Omron CX-Programmer project NewProject (CX-Programmer 7.20)

# PLC NewPLC1: CP1H Y
I/O table (CPU CJ1M-CPU21): rack 0 slot 0 CJ1W-DRM21; rack 0 slot 1 CJ1W-MAD42

## Global symbols (name address type ; comment)
W1.00 BOOL  ; W1.01
CCW_Limit_Flag A540.09 BOOL
CW_Limit_Flag A540.08 BOOL

## Program NewProgram1 (cyclic task 0)
Local symbols
CCW_INPUT 0.01 BOOL
CW_INPUT 0.04 BOOL  ; SMART STEP CW INPUT
ESTOP_PB 1.04 BOOL  ; E-STOP PB
ESTOP_hmi 50.03 BOOL
IN_PSN A280.03 BOOL  ; IN POSITION BIT
JOG_CCW 0.00 BOOL  ; JOG COUNTER CLOCK WISE
JOG_CW 0.10 BOOL  ; JOG CLOCK WISE
JOG_SPD_LWRWRD D0 CHANNEL  ; JOG SPEED LOWER WORD
JOG_SPD_UPRWRD D1 CHANNEL  ; JOG SPEED UPPER WORD
MOVE1_ACCRATE D100 CHANNEL  ; MOVE #1 ACCELERATION RATE
MOVE1_CM W100.05 BOOL  ; MOVE #1 COMPLETE BIT
MOVE1_CM_DELAY W100.06 BOOL  ; MOVE #1 COMPLETE DELAY BIT
MOVE1_CM_DTIM_DN T0000 BOOL  ; MOVE #1 COMPLETE DELAY TIMER DONE BIT
MOVE1_DECELRATE D101 CHANNEL  ; MOVE #1 DECELERATION RATE
MOVE1_FSPD_LWRWRD D102 CHANNEL  ; MOVE #1 FINAL SPEED LOWER WORD
MOVE1_FSPD_UPRWRD D103 CHANNEL  ; MOVE #1 FINAL SPEED UPPER WORD
MOVE1_PSN_LWRWRD D104 CHANNEL  ; MOVE #1 POSITION LOWER WORD
MOVE1_PSN_UPRWRD D105 CHANNEL  ; MOVE #1 POSTION UPPER WORD
MOVE1_ST W100.04 BOOL  ; MOVE #1 START BIT
MOVE1_STSPD_LWRWRD D110 CHANNEL  ; MOVE #1 STARTING SPEED LOWER WORD
MOVE1_STSPD_UPRWRD D111 CHANNEL  ; MOVE # 1 STARTING SPEED UPPER WORD
MOVE2_ACCELRATE D200 CHANNEL  ; MOVE #2 ACCELERATION RATE
MOVE2_CM W100.08 BOOL  ; MOVE #2 COMPLETE BIT
MOVE2_CM_DELAY W100.09 BOOL  ; MOVE #2 COMPLETE DELAY BIT
MOVE2_CM_DTIM_DN T0001 BOOL  ; MOVE #2 COMPLETE DELAY TIMER DONE BIT
MOVE2_DECELRATE D201 CHANNEL  ; MOVE #2 DECELERATION RATE
MOVE2_FSPD_LWRWRD D202 CHANNEL  ; MOVE #2 FINAL SPEED LOWER WORD
MOVE2_FSPD_UPRWRD D203 CHANNEL  ; MOVE #2 FINAL SPEED UPPER WORD
MOVE2_PSN_LWRWRD D204 CHANNEL  ; MOVE #2 POSITION LOWER WORD
MOVE2_PSN_UPRWRD D205 CHANNEL  ; MOVE #2 POSITION UPPER WORD
MOVE2_ST W100.07 BOOL  ; MOVE #2 START BIT
MOVE2_STSPD_LWRWRD D210 CHANNEL  ; MOVE #2 START SPEED LOWER WORD
MOVE2_STSPD_UPRWRD D211 CHANNEL  ; MOVE #2 START SPEED UPPER WORD
MOVE3_ACCELRATE D300 CHANNEL  ; MOVE #3 ACCELERATION RATE
MOVE3_CM W100.11 BOOL  ; MOVE #3 COMPLETE BIT
MOVE3_CM_DELAY W100.12 BOOL  ; MOVE #3 COMPLETE DELAY BIT
MOVE3_CM_DTIM_DN T0002 BOOL  ; MOVE #3 COMPLETE DELAY TIMER  DONE BIT
MOVE3_DECELRATE D301 CHANNEL  ; MOVE #3 DECELERATION RATE
MOVE3_FSPD_LWRWRD D302 CHANNEL  ; MOVE #3 FINAL SPEED LOWER WORD
MOVE3_FSPD_UPRWRD D303 CHANNEL  ; MOVE #3 FINAL SPEED UPPER WORD
MOVE3_PSN_LWRWRD D304 CHANNEL  ; MOVE #3 POSITION LOWER WORD
MOVE3_PSN_UPRWRD D305 CHANNEL  ; MOVE #3 POSITION UPPER WORD
MOVE3_ST W100.10 BOOL  ; MOVE #3 START BIT
MOVE3_STSPD_LWRWRD D310 CHANNEL  ; MOVE #3 START SPEED LOWER WORD
MOVE3_STSPD_UPRWRD D311 CHANNEL  ; MOVE #3 START SPEED UPPER WORD
MOVE4_ACCELRATE D400 CHANNEL  ; MOVE #4 ACCELERATION RATE
MOVE4_CM W100.14 BOOL  ; MOVE #4 COMPLETE BIT
MOVE4_DECELRATE D401 CHANNEL  ; MOVE #4 DECELERATION RATE
MOVE4_FSPD_LWRWRD D402 CHANNEL  ; MOVE #4 FINAL SPEED LOWER WORD
MOVE4_FSPD_UPRWRD D403 CHANNEL  ; MOVE #4 FINAL SPEED UPPER WORD
MOVE4_PSN_LWRWRD D404 CHANNEL  ; MOVE #4 POSITION LOWER WORD
MOVE4_PSN_UPRWRD D405 CHANNEL  ; MOVE #4 POSITION UPPER WORD
MOVE4_ST W100.13 BOOL  ; MOVE #4 START BIT
MOVE4_STSPD_LWRWRD D410 CHANNEL  ; MOVE #4 START SPEED LOWER WORD
MOVE4_STSPD_UPRWRD D411 CHANNEL  ; MOVE #4 START SPEED UPPER WORD
MOVES_RESET W100.15 BOOL  ; MOVES RESET BIT
MOVE_CM A280.03 BOOL  ; MOVE COMPLETE BIT
ORGEN_TS 0.11 BOOL  ; ORIGIN ENABLE TOUCH SWITCH
ORG_EST A280.05 BOOL  ; ORIGIN ESTABLISHED
ORG_SRCHCM W100.01 BOOL  ; ORIGIN SEARCH COMPLETE
ORG_SRCHEN W100.00 BOOL  ; ORIGIN SEARCH ENABLE BIT
PV_LWRWRD A276 CHANNEL  ; PV LOWER WORD
PV_UPRWRD A277 CHANNEL  ; PV UPPER WORD
SSTEP_CCW A540.08 BOOL  ; SMART STEP CCW OVER TRAVEL
SSTEP_CCWEN_OUT 100.00 BOOL  ; SMART STEP CCW ENABLE OUTPUT
SSTEP_CW A540.09 BOOL  ; SMART STEP CW OVER TRAVEL
SSTEP_CWEN_OUT 100.01 BOOL  ; SMART STEP CW ENABLE OUTPUT
SSTEP_HOME W100.02 BOOL  ; SMART STEP HOME
SSTEP_JOGEN W100.03 BOOL  ; SMART STEP JOGGING ENABLE BIT
SSTEP_MOV1EN_TS 0.05 BOOL  ; SMART STEP MOVE #1 ENABLE TOUCH SWITCH
SSTEP_ORGPRX_OUT 100.02 BOOL  ; SMART STEP ORIGIN PROXIMITY OUTPUT
SSTEP_RUNEN_OUT 100.03 BOOL  ; SMART STEP RUN ENABLE OUTPUT
STOP_SPD_LWRWRD D2 CHANNEL  ; STOP SPEED LOWER WORD
STOP_SPD_UPPWRD D3 CHANNEL  ; STOP SPEED UPPER WORD
STPD_ORG A280.06 BOOL  ; STOPPED AT ORIGIN
control_on 75.00 BOOL
convert_pulses D80 DINT
estop_work 60.00 BOOL
go 50.02 BOOL
jog_ccw 50.04 BOOL
jog_cw 50.01 BOOL
jogging_work 60.01 BOOL
latch_rev1 70.00 BOOL
latch_rev2 70.01 BOOL
latch_rev3 70.02 BOOL
latch_rev4 70.03 BOOL
mov1_hmi D250 CHANNEL  ; move 1 position converted for hmi
mov2_hmi D260 CHANNEL  ; move 2 position converted for hmi
mov3_hmi D270 CHANNEL  ; move 3 position converted for hmi
mov4_hmi D280 CHANNEL  ; move 4 position converted for hmi
origin_serach 50.00 BOOL
pulses_good 75.01 BOOL  ; Pulses are over #13CC for /
recipe_controlword D50 CHANNEL  ; gp pro ex recipe control word
rev1_go 60.05 BOOL
rev2_go 60.06 BOOL
rev3_go 60.07 BOOL
rev4_go 60.08 BOOL
revolutions D78 CHANNEL  ; number of revolutions the motor made
smartstep_ccw_jog 50.05 BOOL
temp_off 70.04 BOOL
timer10_done T0010 BOOL
timer11_done T0011 BOOL
timer12_done T0012 BOOL
timer13_done T0013 BOOL

### Section Moves

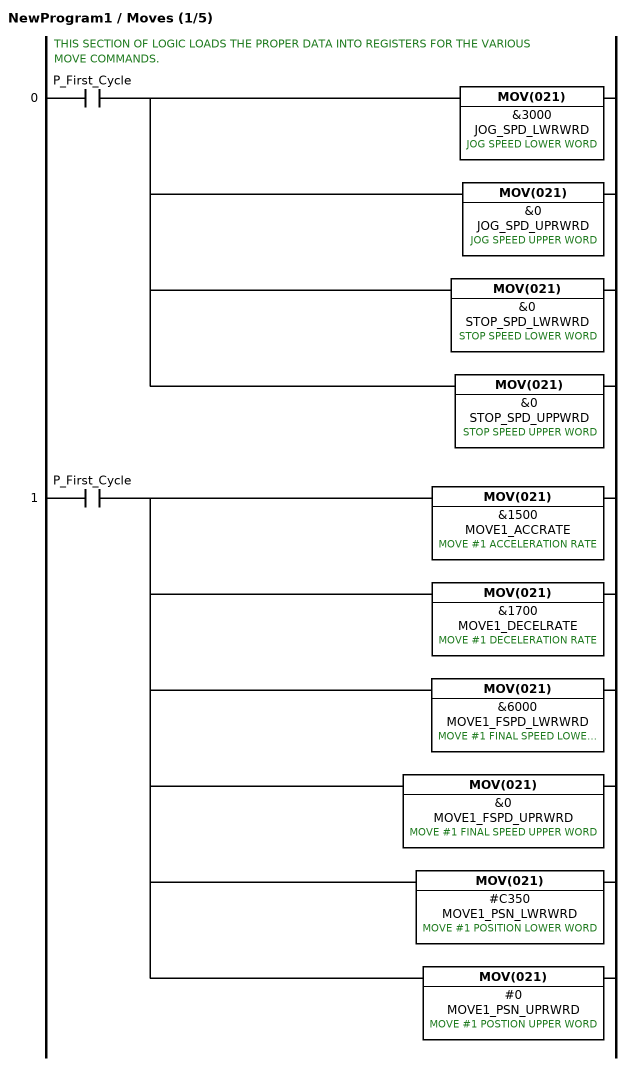
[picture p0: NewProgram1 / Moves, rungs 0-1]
; rung 0: THIS SECTION OF LOGIC LOADS THE PROPER DATA INTO REGISTERS FOR THE VARIOUS MOVE COMMANDS.
LD P_First_Cycle
MOV(021) &3000 JOG_SPD_LWRWRD  ; JOG SPEED LOWER WORD
MOV(021) &0 JOG_SPD_UPRWRD  ; JOG SPEED UPPER WORD
MOV(021) &0 STOP_SPD_LWRWRD  ; STOP SPEED LOWER WORD
MOV(021) &0 STOP_SPD_UPPWRD  ; STOP SPEED UPPER WORD
; rung 1
LD P_First_Cycle
MOV(021) &1500 MOVE1_ACCRATE  ; MOVE #1 ACCELERATION RATE
MOV(021) &1700 MOVE1_DECELRATE  ; MOVE #1 DECELERATION RATE
MOV(021) &6000 MOVE1_FSPD_LWRWRD  ; MOVE #1 FINAL SPEED LOWER WORD
MOV(021) &0 MOVE1_FSPD_UPRWRD  ; MOVE #1 FINAL SPEED UPPER WORD
MOV(021) #C350 MOVE1_PSN_LWRWRD  ; MOVE #1 POSITION LOWER WORD
MOV(021) #0 MOVE1_PSN_UPRWRD  ; MOVE #1 POSTION UPPER WORD

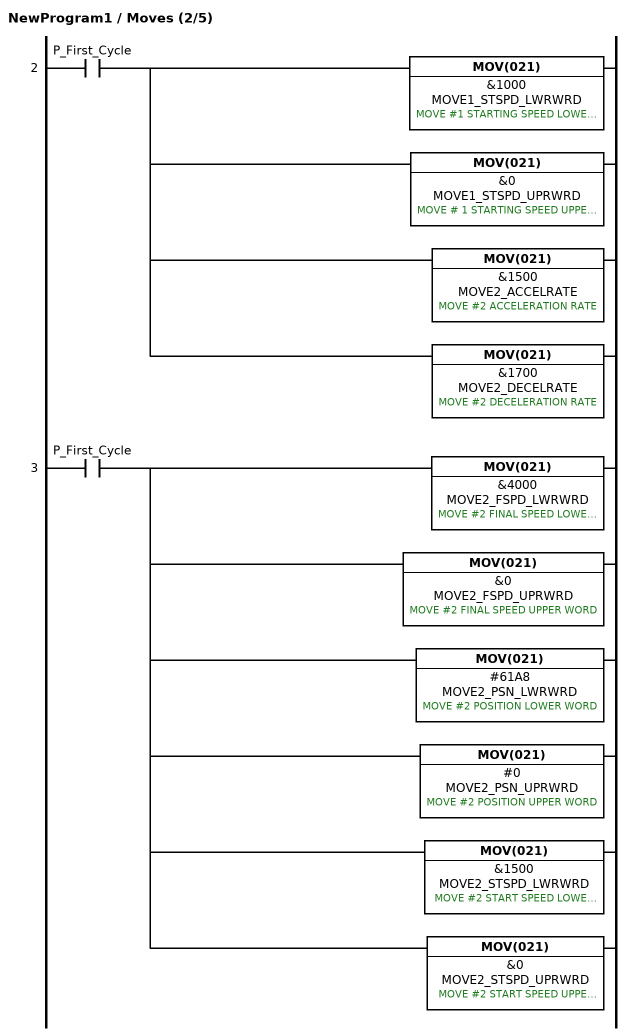
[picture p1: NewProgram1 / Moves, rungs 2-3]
; rung 2
LD P_First_Cycle
MOV(021) &1000 MOVE1_STSPD_LWRWRD  ; MOVE #1 STARTING SPEED LOWER WORD
MOV(021) &0 MOVE1_STSPD_UPRWRD  ; MOVE # 1 STARTING SPEED UPPER WORD
MOV(021) &1500 MOVE2_ACCELRATE  ; MOVE #2 ACCELERATION RATE
MOV(021) &1700 MOVE2_DECELRATE  ; MOVE #2 DECELERATION RATE
; rung 3
LD P_First_Cycle
MOV(021) &4000 MOVE2_FSPD_LWRWRD  ; MOVE #2 FINAL SPEED LOWER WORD
MOV(021) &0 MOVE2_FSPD_UPRWRD  ; MOVE #2 FINAL SPEED UPPER WORD
MOV(021) #61A8 MOVE2_PSN_LWRWRD  ; MOVE #2 POSITION LOWER WORD
MOV(021) #0 MOVE2_PSN_UPRWRD  ; MOVE #2 POSITION UPPER WORD
MOV(021) &1500 MOVE2_STSPD_LWRWRD  ; MOVE #2 START SPEED LOWER WORD
MOV(021) &0 MOVE2_STSPD_UPRWRD  ; MOVE #2 START SPEED UPPER WORD

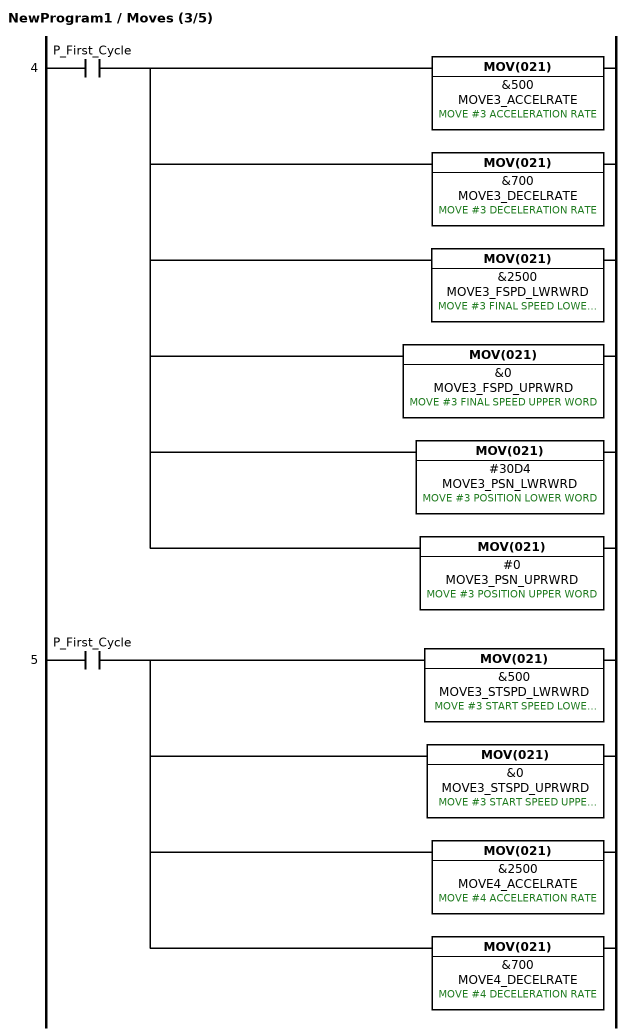
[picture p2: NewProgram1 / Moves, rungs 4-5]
; rung 4
LD P_First_Cycle
MOV(021) &500 MOVE3_ACCELRATE  ; MOVE #3 ACCELERATION RATE
MOV(021) &700 MOVE3_DECELRATE  ; MOVE #3 DECELERATION RATE
MOV(021) &2500 MOVE3_FSPD_LWRWRD  ; MOVE #3 FINAL SPEED LOWER WORD
MOV(021) &0 MOVE3_FSPD_UPRWRD  ; MOVE #3 FINAL SPEED UPPER WORD
MOV(021) #30D4 MOVE3_PSN_LWRWRD  ; MOVE #3 POSITION LOWER WORD
MOV(021) #0 MOVE3_PSN_UPRWRD  ; MOVE #3 POSITION UPPER WORD
; rung 5
LD P_First_Cycle
MOV(021) &500 MOVE3_STSPD_LWRWRD  ; MOVE #3 START SPEED LOWER WORD
MOV(021) &0 MOVE3_STSPD_UPRWRD  ; MOVE #3 START SPEED UPPER WORD
MOV(021) &2500 MOVE4_ACCELRATE  ; MOVE #4 ACCELERATION RATE
MOV(021) &700 MOVE4_DECELRATE  ; MOVE #4 DECELERATION RATE

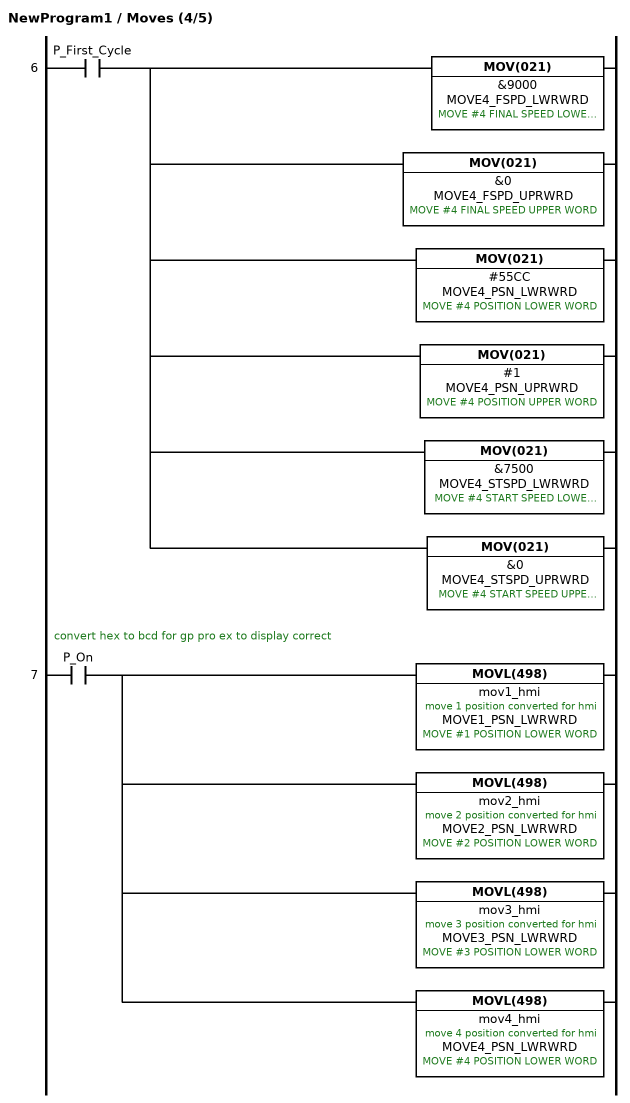
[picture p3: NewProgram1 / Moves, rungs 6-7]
; rung 6
LD P_First_Cycle
MOV(021) &9000 MOVE4_FSPD_LWRWRD  ; MOVE #4 FINAL SPEED LOWER WORD
MOV(021) &0 MOVE4_FSPD_UPRWRD  ; MOVE #4 FINAL SPEED UPPER WORD
MOV(021) #55CC MOVE4_PSN_LWRWRD  ; MOVE #4 POSITION LOWER WORD
MOV(021) #1 MOVE4_PSN_UPRWRD  ; MOVE #4 POSITION UPPER WORD
MOV(021) &7500 MOVE4_STSPD_LWRWRD  ; MOVE #4 START SPEED LOWER WORD
MOV(021) &0 MOVE4_STSPD_UPRWRD  ; MOVE #4 START SPEED UPPER WORD
; rung 7: convert hex to bcd for gp pro ex to display correct
LD P_On
MOVL(498) mov1_hmi MOVE1_PSN_LWRWRD  ; move 1 position converted for hmi, MOVE #1 POSITION LOWER WORD
MOVL(498) mov2_hmi MOVE2_PSN_LWRWRD  ; move 2 position converted for hmi, MOVE #2 POSITION LOWER WORD
MOVL(498) mov3_hmi MOVE3_PSN_LWRWRD  ; move 3 position converted for hmi, MOVE #3 POSITION LOWER WORD
MOVL(498) mov4_hmi MOVE4_PSN_LWRWRD  ; move 4 position converted for hmi, MOVE #4 POSITION LOWER WORD

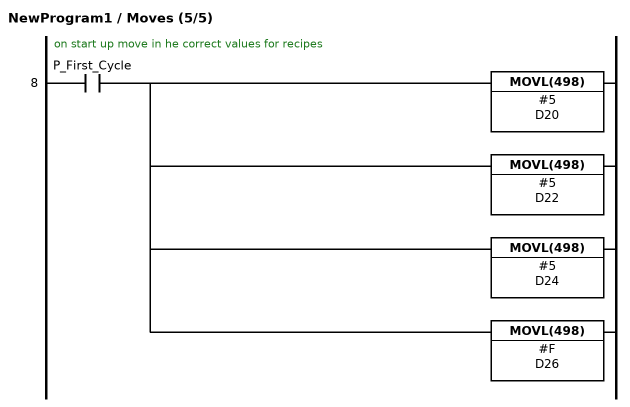
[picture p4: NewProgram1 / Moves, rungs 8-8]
; rung 8: on start up move in he correct values for recipes
LD P_First_Cycle
MOVL(498) #5 D20
MOVL(498) #5 D22
MOVL(498) #5 D24
MOVL(498) #F D26

### Section Main

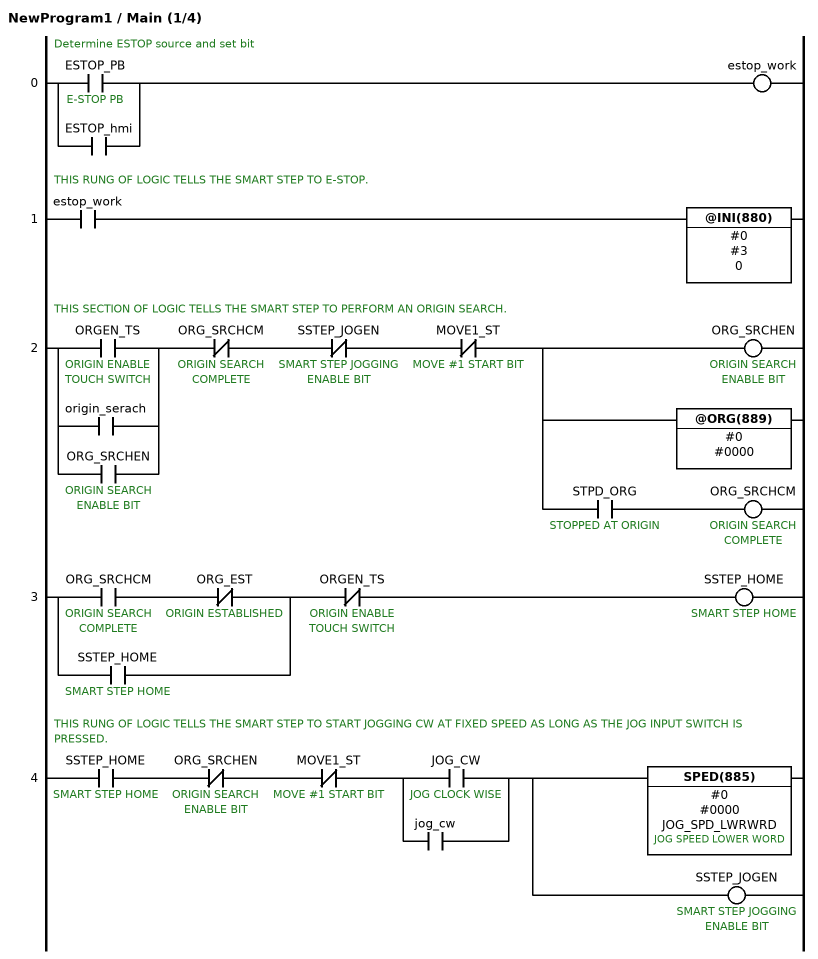
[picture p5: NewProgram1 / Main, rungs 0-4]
; rung 0: Determine ESTOP source and set bit
LD ESTOP_PB  ; E-STOP PB
OR ESTOP_hmi
OUT estop_work
; rung 1: THIS RUNG OF LOGIC TELLS THE SMART STEP TO E-STOP.
LD estop_work
@INI(880) #0 #3 0
; rung 2: THIS SECTION OF LOGIC TELLS THE SMART STEP TO PERFORM AN ORIGIN SEARCH.
LD ORGEN_TS  ; ORIGIN ENABLE TOUCH SWITCH
OR origin_serach
OR ORG_SRCHEN  ; ORIGIN SEARCH ENABLE BIT
ANDNOT ORG_SRCHCM  ; ORIGIN SEARCH COMPLETE
ANDNOT SSTEP_JOGEN  ; SMART STEP JOGGING ENABLE BIT
ANDNOT MOVE1_ST  ; MOVE #1 START BIT
OUT ORG_SRCHEN  ; ORIGIN SEARCH ENABLE BIT
@ORG(889) #0 #0000
AND STPD_ORG  ; STOPPED AT ORIGIN
OUT ORG_SRCHCM  ; ORIGIN SEARCH COMPLETE
; rung 3
LD ORG_SRCHCM  ; ORIGIN SEARCH COMPLETE
ANDNOT ORG_EST  ; ORIGIN ESTABLISHED
OR SSTEP_HOME  ; SMART STEP HOME
ANDNOT ORGEN_TS  ; ORIGIN ENABLE TOUCH SWITCH
OUT SSTEP_HOME  ; SMART STEP HOME
; rung 4: THIS RUNG OF LOGIC TELLS THE SMART STEP TO START JOGGING CW AT FIXED SPEED AS LONG AS THE JOG INPUT SWITCH IS PRESSED.
LD SSTEP_HOME  ; SMART STEP HOME
ANDNOT ORG_SRCHEN  ; ORIGIN SEARCH ENABLE BIT
ANDNOT MOVE1_ST  ; MOVE #1 START BIT
LD JOG_CW  ; JOG CLOCK WISE
OR jog_cw
ANDLD
SPED(885) #0 #0000 JOG_SPD_LWRWRD  ; JOG SPEED LOWER WORD
OUT SSTEP_JOGEN  ; SMART STEP JOGGING ENABLE BIT

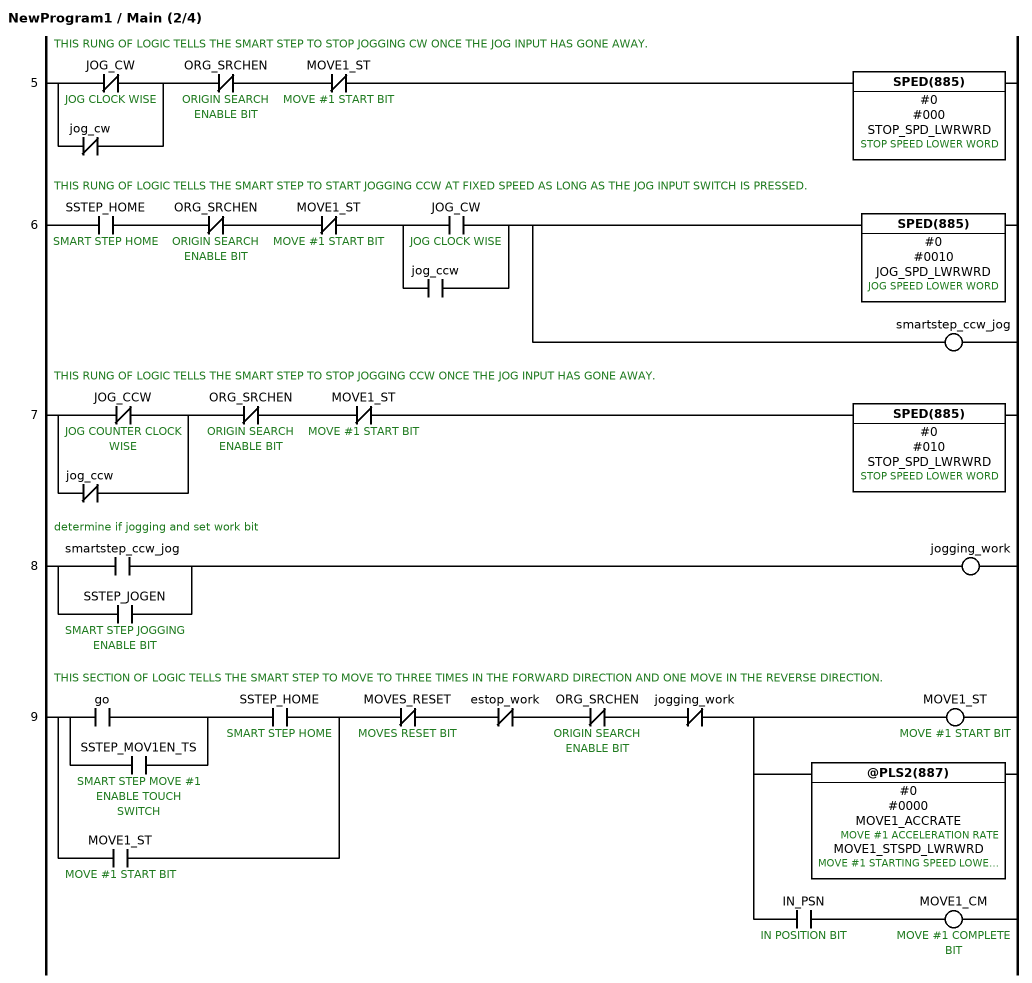
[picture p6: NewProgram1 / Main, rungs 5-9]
; rung 5: THIS RUNG OF LOGIC TELLS THE SMART STEP TO STOP JOGGING CW ONCE THE JOG INPUT HAS GONE AWAY.
LDNOT JOG_CW  ; JOG CLOCK WISE
ORNOT jog_cw
ANDNOT ORG_SRCHEN  ; ORIGIN SEARCH ENABLE BIT
ANDNOT MOVE1_ST  ; MOVE #1 START BIT
SPED(885) #0 #000 STOP_SPD_LWRWRD  ; STOP SPEED LOWER WORD
; rung 6: THIS RUNG OF LOGIC TELLS THE SMART STEP TO START JOGGING CCW AT FIXED SPEED AS LONG AS THE JOG INPUT SWITCH IS PRESSED.
LD SSTEP_HOME  ; SMART STEP HOME
ANDNOT ORG_SRCHEN  ; ORIGIN SEARCH ENABLE BIT
ANDNOT MOVE1_ST  ; MOVE #1 START BIT
LD JOG_CW  ; JOG CLOCK WISE
OR jog_ccw
ANDLD
SPED(885) #0 #0010 JOG_SPD_LWRWRD  ; JOG SPEED LOWER WORD
OUT smartstep_ccw_jog
; rung 7: THIS RUNG OF LOGIC TELLS THE SMART STEP TO STOP JOGGING CCW ONCE THE JOG INPUT HAS GONE AWAY.
LDNOT JOG_CCW  ; JOG COUNTER CLOCK WISE
ORNOT jog_ccw
ANDNOT ORG_SRCHEN  ; ORIGIN SEARCH ENABLE BIT
ANDNOT MOVE1_ST  ; MOVE #1 START BIT
SPED(885) #0 #010 STOP_SPD_LWRWRD  ; STOP SPEED LOWER WORD
; rung 8: determine if jogging and set work bit
LD smartstep_ccw_jog
OR SSTEP_JOGEN  ; SMART STEP JOGGING ENABLE BIT
OUT jogging_work
; rung 9: THIS SECTION OF LOGIC TELLS THE SMART STEP TO MOVE TO THREE TIMES IN THE FORWARD DIRECTION AND ONE MOVE IN THE REVERSE DIRECTION.
LD go
OR SSTEP_MOV1EN_TS  ; SMART STEP MOVE #1 ENABLE TOUCH SWITCH
AND SSTEP_HOME  ; SMART STEP HOME
OR MOVE1_ST  ; MOVE #1 START BIT
ANDNOT MOVES_RESET  ; MOVES RESET BIT
ANDNOT estop_work
ANDNOT ORG_SRCHEN  ; ORIGIN SEARCH ENABLE BIT
ANDNOT jogging_work
OUT MOVE1_ST  ; MOVE #1 START BIT
@PLS2(887) #0 #0000 MOVE1_ACCRATE MOVE1_STSPD_LWRWRD  ; MOVE #1 ACCELERATION RATE, MOVE #1 STARTING SPEED LOWER WORD
AND IN_PSN  ; IN POSITION BIT
OUT MOVE1_CM  ; MOVE #1 COMPLETE BIT

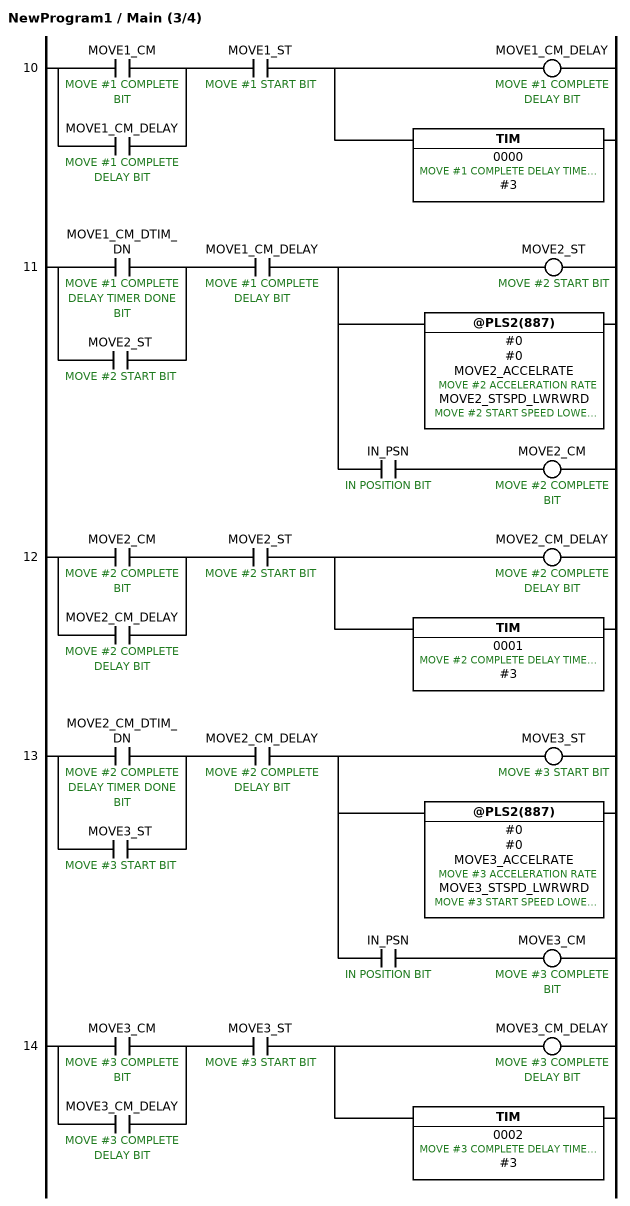
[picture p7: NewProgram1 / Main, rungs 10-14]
; rung 10
LD MOVE1_CM  ; MOVE #1 COMPLETE BIT
OR MOVE1_CM_DELAY  ; MOVE #1 COMPLETE DELAY BIT
AND MOVE1_ST  ; MOVE #1 START BIT
OUT MOVE1_CM_DELAY  ; MOVE #1 COMPLETE DELAY BIT
TIM 0000 #3  ; MOVE #1 COMPLETE DELAY TIMER DONE BIT
; rung 11
LD MOVE1_CM_DTIM_DN  ; MOVE #1 COMPLETE DELAY TIMER DONE BIT
OR MOVE2_ST  ; MOVE #2 START BIT
AND MOVE1_CM_DELAY  ; MOVE #1 COMPLETE DELAY BIT
OUT MOVE2_ST  ; MOVE #2 START BIT
@PLS2(887) #0 #0 MOVE2_ACCELRATE MOVE2_STSPD_LWRWRD  ; MOVE #2 ACCELERATION RATE, MOVE #2 START SPEED LOWER WORD
AND IN_PSN  ; IN POSITION BIT
OUT MOVE2_CM  ; MOVE #2 COMPLETE BIT
; rung 12
LD MOVE2_CM  ; MOVE #2 COMPLETE BIT
OR MOVE2_CM_DELAY  ; MOVE #2 COMPLETE DELAY BIT
AND MOVE2_ST  ; MOVE #2 START BIT
OUT MOVE2_CM_DELAY  ; MOVE #2 COMPLETE DELAY BIT
TIM 0001 #3  ; MOVE #2 COMPLETE DELAY TIMER DONE BIT
; rung 13
LD MOVE2_CM_DTIM_DN  ; MOVE #2 COMPLETE DELAY TIMER DONE BIT
OR MOVE3_ST  ; MOVE #3 START BIT
AND MOVE2_CM_DELAY  ; MOVE #2 COMPLETE DELAY BIT
OUT MOVE3_ST  ; MOVE #3 START BIT
@PLS2(887) #0 #0 MOVE3_ACCELRATE MOVE3_STSPD_LWRWRD  ; MOVE #3 ACCELERATION RATE, MOVE #3 START SPEED LOWER WORD
AND IN_PSN  ; IN POSITION BIT
OUT MOVE3_CM  ; MOVE #3 COMPLETE BIT
; rung 14
LD MOVE3_CM  ; MOVE #3 COMPLETE BIT
OR MOVE3_CM_DELAY  ; MOVE #3 COMPLETE DELAY BIT
AND MOVE3_ST  ; MOVE #3 START BIT
OUT MOVE3_CM_DELAY  ; MOVE #3 COMPLETE DELAY BIT
TIM 0002 #3  ; MOVE #3 COMPLETE DELAY TIMER  DONE BIT

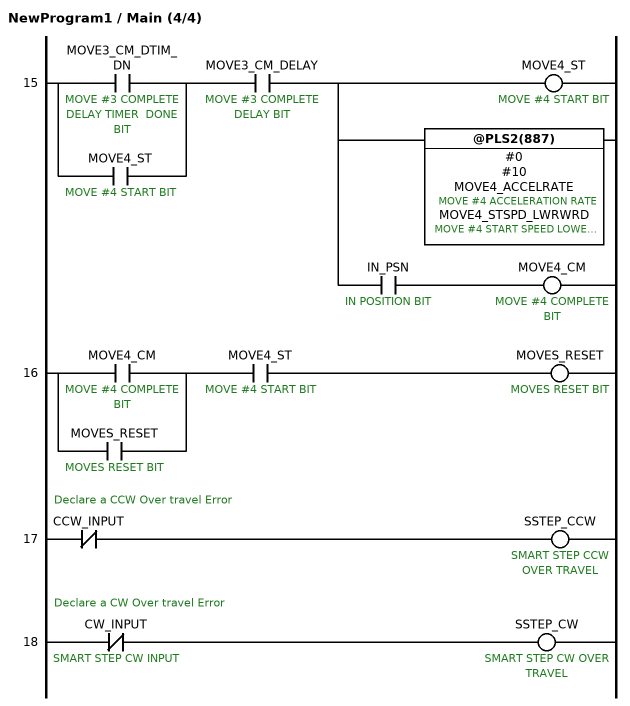
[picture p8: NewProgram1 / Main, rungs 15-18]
; rung 15
LD MOVE3_CM_DTIM_DN  ; MOVE #3 COMPLETE DELAY TIMER  DONE BIT
OR MOVE4_ST  ; MOVE #4 START BIT
AND MOVE3_CM_DELAY  ; MOVE #3 COMPLETE DELAY BIT
OUT MOVE4_ST  ; MOVE #4 START BIT
@PLS2(887) #0 #10 MOVE4_ACCELRATE MOVE4_STSPD_LWRWRD  ; MOVE #4 ACCELERATION RATE, MOVE #4 START SPEED LOWER WORD
AND IN_PSN  ; IN POSITION BIT
OUT MOVE4_CM  ; MOVE #4 COMPLETE BIT
; rung 16
LD MOVE4_CM  ; MOVE #4 COMPLETE BIT
OR MOVES_RESET  ; MOVES RESET BIT
AND MOVE4_ST  ; MOVE #4 START BIT
OUT MOVES_RESET  ; MOVES RESET BIT
; rung 17: Declare a CCW Over travel Error
LDNOT CCW_INPUT
OUT SSTEP_CCW  ; SMART STEP CCW OVER TRAVEL
; rung 18: Declare a CW Over travel Error
LDNOT CW_INPUT  ; SMART STEP CW INPUT
OUT SSTEP_CW  ; SMART STEP CW OVER TRAVEL

### Section recipes

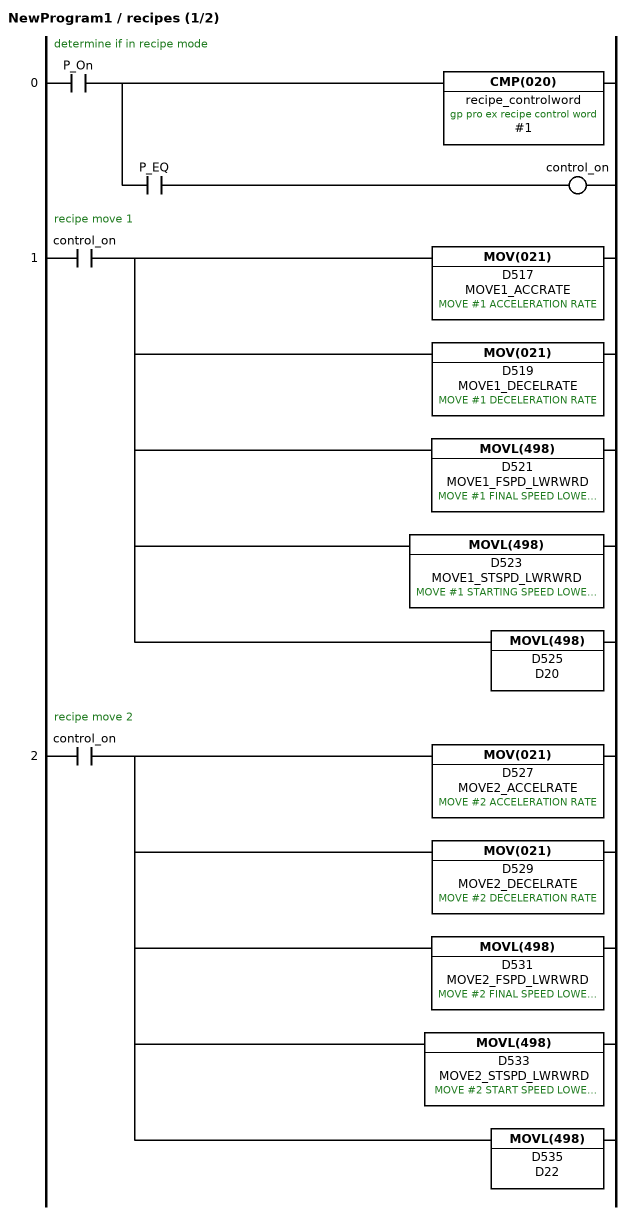
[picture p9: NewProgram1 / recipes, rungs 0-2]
; rung 0: determine if in recipe mode
LD P_On
CMP(020) recipe_controlword #1  ; gp pro ex recipe control word
AND P_EQ
OUT control_on
; rung 1: recipe move 1
LD control_on
MOV(021) D517 MOVE1_ACCRATE  ; MOVE #1 ACCELERATION RATE
MOV(021) D519 MOVE1_DECELRATE  ; MOVE #1 DECELERATION RATE
MOVL(498) D521 MOVE1_FSPD_LWRWRD  ; MOVE #1 FINAL SPEED LOWER WORD
MOVL(498) D523 MOVE1_STSPD_LWRWRD  ; MOVE #1 STARTING SPEED LOWER WORD
MOVL(498) D525 D20
; rung 2: recipe move 2
LD control_on
MOV(021) D527 MOVE2_ACCELRATE  ; MOVE #2 ACCELERATION RATE
MOV(021) D529 MOVE2_DECELRATE  ; MOVE #2 DECELERATION RATE
MOVL(498) D531 MOVE2_FSPD_LWRWRD  ; MOVE #2 FINAL SPEED LOWER WORD
MOVL(498) D533 MOVE2_STSPD_LWRWRD  ; MOVE #2 START SPEED LOWER WORD
MOVL(498) D535 D22

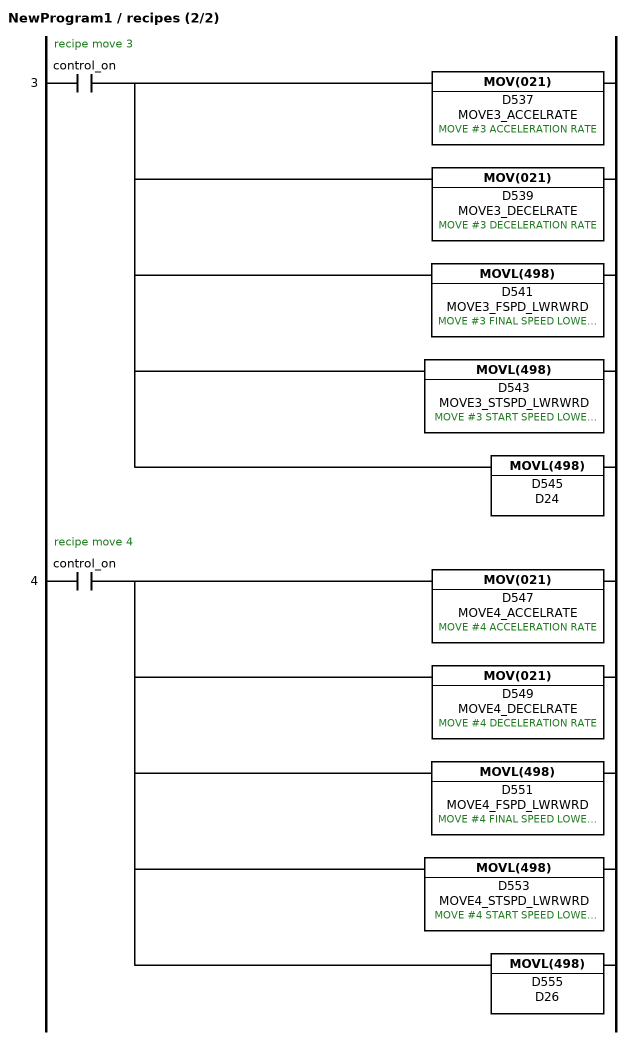
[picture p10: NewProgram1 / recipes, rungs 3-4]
; rung 3: recipe move 3
LD control_on
MOV(021) D537 MOVE3_ACCELRATE  ; MOVE #3 ACCELERATION RATE
MOV(021) D539 MOVE3_DECELRATE  ; MOVE #3 DECELERATION RATE
MOVL(498) D541 MOVE3_FSPD_LWRWRD  ; MOVE #3 FINAL SPEED LOWER WORD
MOVL(498) D543 MOVE3_STSPD_LWRWRD  ; MOVE #3 START SPEED LOWER WORD
MOVL(498) D545 D24
; rung 4: recipe move 4
LD control_on
MOV(021) D547 MOVE4_ACCELRATE  ; MOVE #4 ACCELERATION RATE
MOV(021) D549 MOVE4_DECELRATE  ; MOVE #4 DECELERATION RATE
MOVL(498) D551 MOVE4_FSPD_LWRWRD  ; MOVE #4 FINAL SPEED LOWER WORD
MOVL(498) D553 MOVE4_STSPD_LWRWRD  ; MOVE #4 START SPEED LOWER WORD
MOVL(498) D555 D26

### Section revs_convert

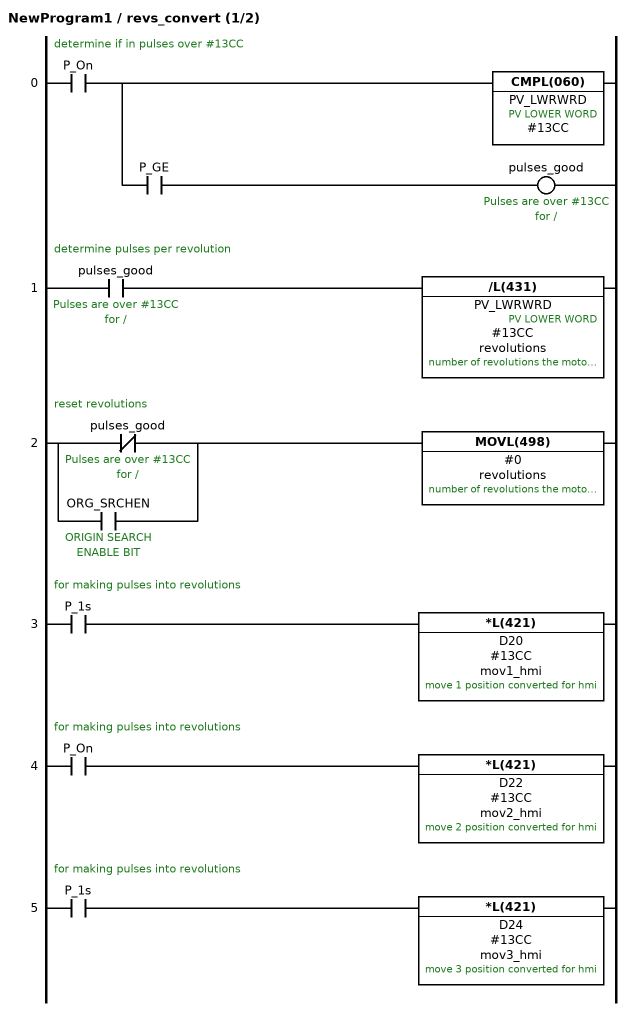
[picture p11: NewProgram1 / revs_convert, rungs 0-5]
; rung 0: determine if in pulses over #13CC
LD P_On
CMPL(060) PV_LWRWRD #13CC  ; PV LOWER WORD
AND P_GE
OUT pulses_good  ; Pulses are over #13CC for /
; rung 1: determine pulses per revolution
LD pulses_good  ; Pulses are over #13CC for /
/L(431) PV_LWRWRD #13CC revolutions  ; PV LOWER WORD, number of revolutions the motor made
; rung 2: reset revolutions
LDNOT pulses_good  ; Pulses are over #13CC for /
OR ORG_SRCHEN  ; ORIGIN SEARCH ENABLE BIT
MOVL(498) #0 revolutions  ; number of revolutions the motor made
; rung 3: for making pulses into revolutions
LD P_1s
*L(421) D20 #13CC mov1_hmi  ; move 1 position converted for hmi
; rung 4: for making pulses into revolutions
LD P_On
*L(421) D22 #13CC mov2_hmi  ; move 2 position converted for hmi
; rung 5: for making pulses into revolutions
LD P_1s
*L(421) D24 #13CC mov3_hmi  ; move 3 position converted for hmi

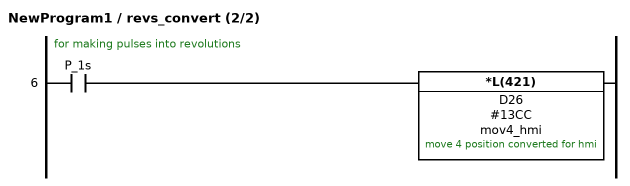
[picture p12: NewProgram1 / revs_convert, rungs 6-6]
; rung 6: for making pulses into revolutions
LD P_1s
*L(421) D26 #13CC mov4_hmi  ; move 4 position converted for hmi

### Section END
; rung 0
END(001)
